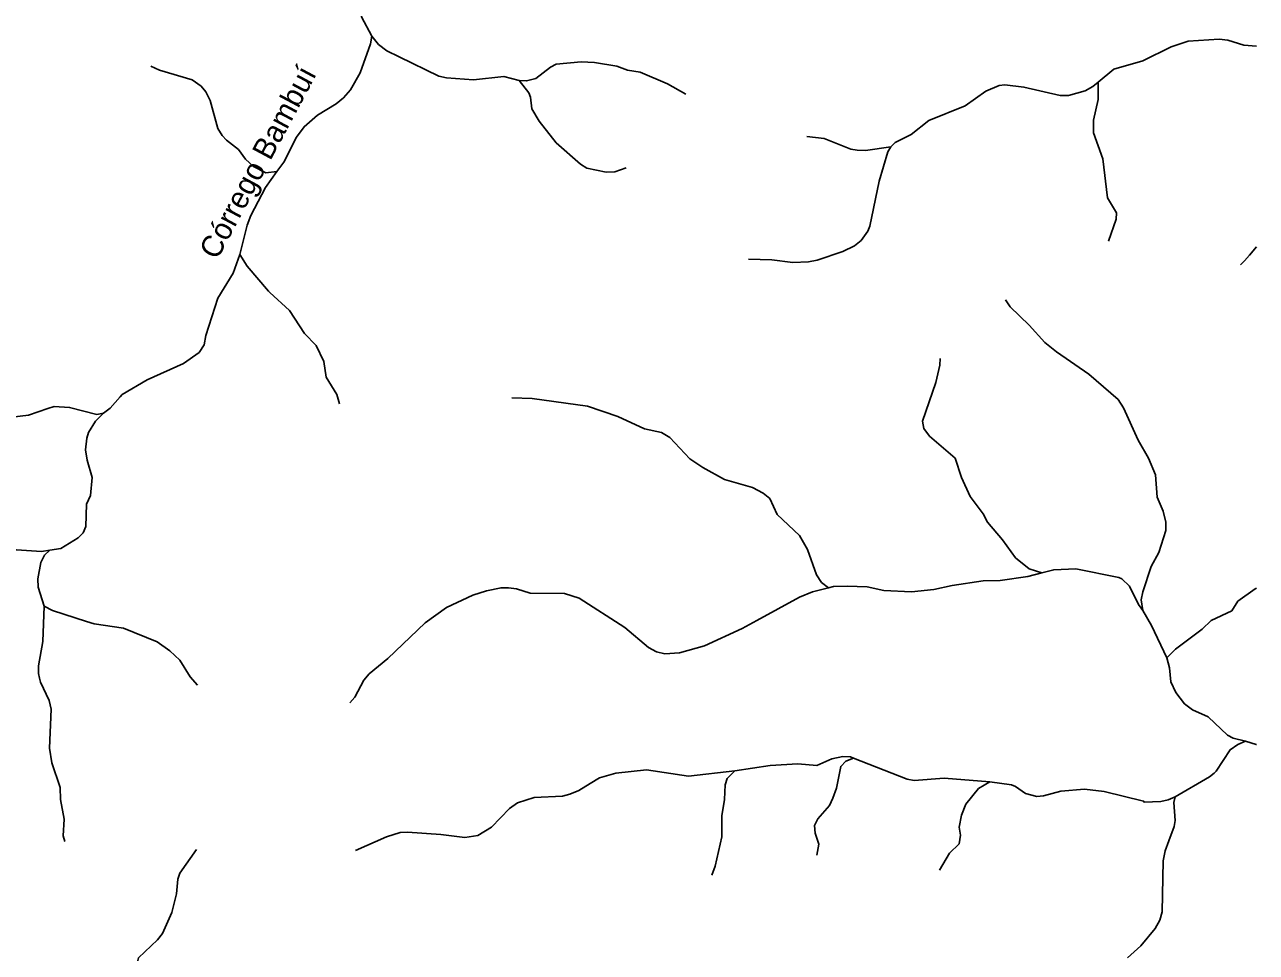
# Model space of a CAD drawing. Extents: x 473.9 to 500, y 7733.1 to 7760.8.
# Drawn here: x 494.3 to 500, y 7748.41 to 7752.7 of the extents above; entities that cross this region are included whole.
import ezdxf
from ezdxf.enums import TextEntityAlignment as Align

# ---------------------------------------------------------------- set-up
doc = ezdxf.new("R2010")
doc.units = 0
doc.header["$LTSCALE"] = 0.032
doc.layers.add('61', color=7, linetype='Continuous')
doc.layers.add('7', color=7, linetype='Continuous', lineweight=25)

msp = doc.modelspace()

# ---------------------------------------------------------------- linework, layer by layer
at = {"layer": '7'}
for points in [[(495.9073, 7752.6441), (495.8604, 7752.733), (495.8452, 7752.8028), (495.8185, 7752.8459), (495.7255, 7752.9317), (495.7081, 7752.9627), (495.7073, 7753.0002), (495.7207, 7753.0317), (495.7275, 7753.1203), (495.7441, 7753.2053), (495.7432, 7753.2352), (495.7162, 7753.3352), (495.7297, 7753.4073), (495.7306, 7753.4653), (495.7567, 7753.5076), (495.8254, 7753.5691), (495.8323, 7753.5828), (495.8354, 7753.6113), (495.805, 7753.6569), (495.8051, 7753.6711)], [(495.4678, 7752.0178), (495.5008, 7752.0613), (495.5601, 7752.1768), (495.5948, 7752.2248), (495.6562, 7752.2789), (495.7436, 7752.331), (495.7767, 7752.3578), (495.8095, 7752.396), (495.8547, 7752.474), (495.9019, 7752.6087), (495.9073, 7752.6441)], [(496.5891, 7752.4378), (496.5182, 7752.4575), (496.3779, 7752.4408), (496.2537, 7752.4501), (496.2177, 7752.4587), (496.0339, 7752.5482), (495.9771, 7752.5759), (495.9388, 7752.6053), (495.9073, 7752.6441)], [(499.2683, 7752.431), (499.34, 7752.491), (499.4747, 7752.5289), (499.6058, 7752.594), (499.6845, 7752.6204), (499.8272, 7752.6291), (499.8674, 7752.6243), (499.9419, 7752.6016), (500, 7752.5965)], [(494.8854, 7752.5054), (494.9253, 7752.4862), (495.0764, 7752.4418), (495.1182, 7752.4124), (495.1398, 7752.386), (495.1595, 7752.3464), (495.1962, 7752.2172), (495.2152, 7752.1847), (495.235, 7752.1626), (495.2919, 7752.1192), (495.324, 7752.0744), (495.3602, 7752.0401), (495.4174, 7752.0122), (495.4678, 7752.0178)], [(497.3602, 7752.3748), (497.2763, 7752.4238), (497.1497, 7752.4767), (497.0908, 7752.4865), (497.0419, 7752.505), (496.9379, 7752.5216), (496.8771, 7752.5242), (496.7614, 7752.5137), (496.735, 7752.5007), (496.6673, 7752.4473), (496.6236, 7752.4368), (496.5891, 7752.4378)], [(497.0849, 7752.0341), (497.0324, 7752.0163), (496.9927, 7752.0142), (496.9021, 7752.0324), (496.8728, 7752.0521), (496.7605, 7752.1508), (496.6824, 7752.2504), (496.6484, 7752.3074), (496.6421, 7752.361), (496.6339, 7752.3819), (496.5891, 7752.4378)], [(498.3093, 7752.1324), (498.329, 7752.1522), (498.4034, 7752.1882), (498.4849, 7752.2532), (498.653, 7752.322), (498.749, 7752.3898), (498.8094, 7752.4157), (498.8362, 7752.419), (498.9244, 7752.408), (499.0928, 7752.3685), (499.1313, 7752.3694), (499.2078, 7752.3902), (499.2435, 7752.4102), (499.2683, 7752.431)], [(499.3153, 7751.6957), (499.3521, 7751.7976), (499.3537, 7751.8261), (499.3116, 7751.8955), (499.2896, 7752.0755), (499.2472, 7752.1963), (499.2471, 7752.2544), (499.2688, 7752.3506), (499.2683, 7752.431)], [(497.6503, 7751.6124), (497.7585, 7751.6084), (497.855, 7751.5973), (497.9288, 7751.6005), (497.968, 7751.6076), (498.0876, 7751.6473), (498.1402, 7751.6744), (498.1715, 7751.6986), (498.2029, 7751.7417), (498.2123, 7751.7647), (498.2546, 7751.9727), (498.2944, 7752.1081), (498.3093, 7752.1324)], [(497.9197, 7752.1789), (497.9998, 7752.1698), (498.1241, 7752.1216), (498.1538, 7752.1158), (498.1917, 7752.115), (498.3093, 7752.1324)], [(495.297, 7751.6339), (495.3317, 7751.7691), (495.3487, 7751.8134), (495.4153, 7751.9433), (495.4678, 7752.0178)], [(494.6673, 7750.8998), (494.6973, 7750.9233), (494.7442, 7750.9754), (494.7534, 7750.9856), (494.8687, 7751.0536), (495.0364, 7751.1303), (495.1085, 7751.1806), (495.1317, 7751.2159), (495.1403, 7751.2584), (495.1959, 7751.4323), (495.2658, 7751.5482), (495.297, 7751.6339)], [(495.7578, 7750.9431), (495.7456, 7750.9868), (495.6963, 7751.0658), (495.6853, 7751.1387), (495.6509, 7751.2133), (495.5968, 7751.2678), (495.5265, 7751.3754), (495.4361, 7751.4579), (495.4299, 7751.4636), (495.3311, 7751.5803), (495.297, 7751.6339)], [(499.9272, 7751.5864), (499.9448, 7751.605), (499.9687, 7751.6309), (500, 7751.6699)], [(498.8399, 7751.424), (498.8607, 7751.3925), (498.9494, 7751.3073), (499.0216, 7751.227), (499.0758, 7751.1831), (499.2253, 7751.0802), (499.3604, 7750.9636), (499.385, 7750.9253), (499.4534, 7750.7755), (499.5017, 7750.6922), (499.5333, 7750.6142), (499.5407, 7750.5117), (499.5686, 7750.4474), (499.5806, 7750.3965), (499.5814, 7750.3576), (499.5481, 7750.2557), (499.5128, 7750.1916), (499.4753, 7750.0742), (499.4677, 7750.0365), (499.4753, 7749.988)], [(498.5374, 7751.1532), (498.5361, 7751.1217), (498.5175, 7751.0425), (498.4559, 7750.8635), (498.4616, 7750.8289), (498.4879, 7750.7938), (498.6065, 7750.6912), (498.6356, 7750.6024), (498.6764, 7750.5145), (498.736, 7750.4337), (498.7561, 7750.3956), (498.8256, 7750.3149), (498.886, 7750.2305), (498.949, 7750.18), (499.0068, 7750.1613)], [(493.7905, 7750.939), (493.8997, 7750.9054), (493.954, 7750.9029), (494.0511, 7750.8812), (494.138, 7750.8693), (494.3198, 7750.8913), (494.4091, 7750.9209), (494.4388, 7750.9308), (494.5097, 7750.9269), (494.635, 7750.8941), (494.6673, 7750.8998)], [(496.5554, 7750.9715), (496.6492, 7750.9678), (496.9055, 7750.9325), (497.0465, 7750.8851), (497.1694, 7750.8274), (497.2483, 7750.8098), (497.2871, 7750.7872), (497.3796, 7750.6891), (497.4386, 7750.6489), (497.5389, 7750.5939), (497.6687, 7750.5556), (497.7191, 7750.5296), (497.7486, 7750.506), (497.7829, 7750.4316), (497.8861, 7750.3343), (497.9228, 7750.2691), (497.9657, 7750.1529), (497.9881, 7750.1174), (498.0206, 7750.0925)], [(494.4179, 7750.2662), (494.4697, 7750.2748), (494.5501, 7750.3229), (494.5732, 7750.3473), (494.5852, 7750.3757), (494.5881, 7750.4795), (494.6072, 7750.5196), (494.6135, 7750.6022), (494.5904, 7750.682), (494.584, 7750.731), (494.5888, 7750.7839), (494.5978, 7750.8101), (494.6299, 7750.8631), (494.6673, 7750.8998)], [(494.0813, 7750.088), (494.1534, 7750.1295), (494.1716, 7750.1938), (494.1859, 7750.2224), (494.219, 7750.2588), (494.2637, 7750.2686), (494.38, 7750.2599), (494.4179, 7750.2662)], [(494.3919, 7750.007), (494.3637, 7750.0956), (494.3627, 7750.1344), (494.3774, 7750.2092), (494.3942, 7750.2425), (494.4179, 7750.2662)], [(498.0206, 7750.0925), (498.0445, 7750.0987), (498.1065, 7750.1004), (498.1992, 7750.0971), (498.2766, 7750.0802), (498.4048, 7750.0731), (498.5075, 7750.0843), (498.593, 7750.1034), (498.7357, 7750.1243), (498.8153, 7750.1261), (498.942, 7750.1445), (499.0068, 7750.1613)], [(499.0068, 7750.1613), (499.0626, 7750.1757), (499.1645, 7750.1804), (499.3643, 7750.1397), (499.3778, 7750.1339), (499.4137, 7750.1006), (499.4548, 7750.0148), (499.4753, 7749.988)], [(495.8063, 7749.5606), (495.8291, 7749.5864), (495.8713, 7749.6655), (495.8963, 7749.6944), (495.9821, 7749.7649), (496.1551, 7749.93), (496.2541, 7750.0016), (496.3749, 7750.059), (496.4385, 7750.0778), (496.5058, 7750.0922), (496.5402, 7750.0922), (496.5777, 7750.0875), (496.64, 7750.0678), (496.7987, 7750.0659), (496.8673, 7750.0439), (497.0778, 7749.9091), (497.1873, 7749.817), (497.2252, 7749.7959), (497.2632, 7749.7877), (497.332, 7749.7909), (497.4465, 7749.8243), (497.6209, 7749.9037), (497.6891, 7749.941), (497.8868, 7750.0492), (497.9469, 7750.0734), (498.0206, 7750.0925)], [(500, 7750.0913), (499.994, 7750.087), (499.9143, 7750.0298), (499.8861, 7749.9858), (499.7902, 7749.9409), (499.7485, 7749.9017), (499.6254, 7749.8089), (499.5861, 7749.7683)], [(494.4883, 7748.9198), (494.4807, 7748.9456), (494.4846, 7749.0228), (494.467, 7749.1126), (494.4654, 7749.1691), (494.4283, 7749.2824), (494.4171, 7749.3502), (494.4245, 7749.5315), (494.4154, 7749.571), (494.3758, 7749.6563), (494.371, 7749.6744), (494.3652, 7749.6963), (494.3652, 7749.7311), (494.3852, 7749.8433), (494.3919, 7750.007)], [(495.1007, 7749.6421), (495.0671, 7749.6803), (495.0191, 7749.7574), (494.9739, 7749.8002), (494.9154, 7749.8428), (494.7586, 7749.9052), (494.6229, 7749.9256), (494.5883, 7749.9366), (494.4302, 7749.9867), (494.3919, 7750.007)], [(499.4753, 7749.988), (499.5151, 7749.918), (499.5861, 7749.7683)], [(499.5861, 7749.7683), (499.5975, 7749.7226), (499.6036, 7749.6573), (499.6273, 7749.6084), (499.667, 7749.5562), (499.7052, 7749.5277), (499.777, 7749.4956), (499.8666, 7749.4115), (499.8923, 7749.3965), (499.9491, 7749.3828)], [(499.6239, 7749.1253), (499.7838, 7749.2185), (499.8043, 7749.2358), (499.814, 7749.244), (499.8795, 7749.3432), (499.9146, 7749.3684), (499.9491, 7749.3828)], [(499.9491, 7749.3828), (499.9993, 7749.3683), (500, 7749.3681)], [(497.5871, 7749.2454), (497.7511, 7749.2712), (497.8788, 7749.2785), (497.9659, 7749.2705), (498.0353, 7749.3016), (498.0866, 7749.3121), (498.1218, 7749.3105), (498.1359, 7749.3043)], [(497.9659, 7748.8566), (497.9763, 7748.9061), (497.9587, 7748.9574), (497.9555, 7748.9935), (497.972, 7749.0241), (498.0246, 7749.0863), (498.0411, 7749.1194), (498.0583, 7749.1653), (498.0775, 7749.2659), (498.1008, 7749.2913), (498.1359, 7749.3043)], [(498.1359, 7749.3043), (498.3852, 7749.2067), (498.417, 7749.2008), (498.5556, 7749.2127), (498.7662, 7749.1948)], [(495.833, 7748.8773), (495.9765, 7748.9404), (496.0392, 7748.9601), (496.0736, 7748.9625), (496.2265, 7748.9514), (496.338, 7748.9378), (496.3984, 7748.9461), (496.4622, 7748.9853), (496.5441, 7749.0714), (496.5815, 7749.0982), (496.6591, 7749.1228), (496.7902, 7749.1292), (496.8243, 7749.1379), (496.8652, 7749.1555), (496.9175, 7749.1869), (496.9611, 7749.213), (497.037, 7749.2352), (497.1781, 7749.2512), (497.373, 7749.2216), (497.5871, 7749.2454)], [(497.4808, 7748.7635), (497.4969, 7748.8057), (497.5272, 7748.9411), (497.5274, 7749.0379), (497.5402, 7749.114), (497.5418, 7749.181), (497.5516, 7749.2105), (497.5871, 7749.2454)], [(498.534, 7748.7857), (498.5809, 7748.8653), (498.6258, 7748.9087), (498.6306, 7748.9486), (498.625, 7748.9853), (498.6358, 7749.0413), (498.6555, 7749.0924), (498.7149, 7749.1636), (498.7662, 7749.1948)], [(498.7662, 7749.1948), (498.8676, 7749.1807), (498.8861, 7749.1738), (498.9313, 7749.1408), (498.9838, 7749.1278), (499.0159, 7749.1307), (499.0949, 7749.1525), (499.2046, 7749.1614), (499.2965, 7749.1497), (499.4782, 7749.1061), (499.4802, 7749.1016), (499.5574, 7749.1045), (499.5918, 7749.1112), (499.6239, 7749.1253)], [(499.4041, 7748.381), (499.4649, 7748.4372), (499.5321, 7748.5162), (499.5541, 7748.5549), (499.5638, 7748.5934), (499.5693, 7748.83), (499.5781, 7748.8757), (499.5952, 7748.9218), (499.62, 7748.9886), (499.624, 7749.016), (499.6183, 7749.0995), (499.6239, 7749.1253)], [(495.0964, 7748.8813), (495.0191, 7748.7727), (495.0098, 7748.7448), (495.0048, 7748.6765), (494.9833, 7748.5909), (494.9397, 7748.4943), (494.9165, 7748.4644), (494.8281, 7748.3809), (494.8196, 7748.3438), (494.8415, 7748.3001), (494.9062, 7748.2108), (495.0091, 7748.0145), (495.0184, 7747.9927), (495.0514, 7747.817), (495.0521, 7747.8135), (495.0609, 7747.7906), (495.0881, 7747.7449), (495.1348, 7747.6909), (495.1595, 7747.6239), (495.1916, 7747.5788)]]:
    msp.add_lwpolyline(points, dxfattribs=at)

# ---------------------------------------------------------------- texts
at = {"layer": '61'}
msp.add_text('Córrego Bambuí', height=0.1, rotation=61.876, dxfattribs=at).set_placement((495.4239, 7752.0377), align=Align.CENTER)

doc.saveas('drawing.dxf')
